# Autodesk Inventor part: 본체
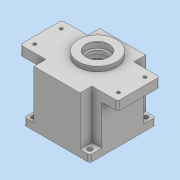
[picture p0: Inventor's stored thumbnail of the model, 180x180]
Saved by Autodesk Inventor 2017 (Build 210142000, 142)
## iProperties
Part Number: 본체
Material: 일반
Document SubType Name: Modeling
Designer: user
Density: 1 g/cm^3
Appearance: 기본값
Mass: 324.576 g
Surface Area: 793.925 cm^2
Volume: 324.576 cm^3
Author: user
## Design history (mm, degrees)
sketch "스케치1"
  geometry: L1 (-70, -30)-(70, -30); L2 (70, -30)-(70, 30); L3 (70, 30)-(-70, 30); L4 (-70, 30)-(-70, -30); L5 (-70, -30)-(70, 30); L6 (70, -30)-(-70, 30); L7 (-33, -47)-(33, -47); L8 (33, -47)-(33, 47); L9 (33, 47)-(-33, 47); L10 (-33, 47)-(-33, -47); L11 (-33, -47)-(33, 47); L12 (33, -47)-(-33, 47); 1 further point
  constraints: 24 end point, 4 midpoint, 4 parallel, 2 horizontal, 2 perpendicular
  dimensions: "d0" = 140 distance of L3.end L2.end; "d1" = 60 distance of L2.end L1.end; "d2" = 66 distance of L9.end L8.end; "d3" = 94 distance of L8.end L7.end
extrude "돌출1" new body sketch "스케치1" distance "d4" = 13; taper "d5" = 0 deg
sketch "스케치2"
  geometry: L1 (33, 47)-(-33, 47); L2 (-33, 47)-(-33, -47); L3 (-33, -47)-(33, -47); L4 (33, -47)-(33, 47); L5 (33, 47)-(-33, -47); L6 (-33, 47)-(33, -47); L7 (47, 30)-(-47, 30); L8 (-47, 30)-(-47, -30); L9 (-47, -30)-(47, -30); L10 (47, -30)-(47, 30); L11 (47, 30)-(-47, -30); L12 (-47, 30)-(47, -30); 1 further point
  constraints: 24 end point, 4 midpoint, 4 parallel, 2 horizontal, 2 perpendicular
  dimensions: "d6" = 66 distance of L3.end L2.end; "d7" = 94 distance of L2.end L1.end; "d8" = 94 distance of L9.end L8.end; "d9" = 60 distance of L8.end L7.end
extrude "돌출2" join sketch "스케치2" distance "d10" = 57; taper "d11" = 0 deg
sketch "스케치3"
  geometry: L1 (47, 47)-(-47, 47); L2 (-47, 47)-(-47, -47); L3 (-47, -47)-(47, -47); L4 (47, -47)-(47, 47); L5 (47, 47)-(-47, -47); L6 (-47, 47)-(47, -47); 1 further point
  constraints: 12 end point, 2 midpoint, 2 parallel, 1 horizontal, 1 perpendicular
  dimensions: "d12" = 94 distance of L3.end L2.end; "d13" = 94 distance of L2.end L1.end
extrude "돌출3" join sketch "스케치3" distance "d14" = 10; taper "d15" = 0 deg
sketch "스케치4"
  geometry: C1 r 27.5 at (0, 11); 1 further point
  constraints: 1 centre point, 1 vertical alignment
  dimensions: "d16" = 55 diameter of C1; "d17" = 11 distance of point (0, 0) C1.centre
extrude "돌출4" join sketch "스케치4" distance "d18" = 7; taper "d19" = 0 deg
sketch "스케치5"
  geometry: C1 r 16 at (0, 0); 1 further point
  constraints: 1 centre point
  dimensions: "d20" = 32 diameter of C1
extrude "돌출5" cut sketch "스케치5" distance "d21" = 8.3; taper "d22" = 0 deg
sketch "스케치6"
  geometry: C1 r 16 at (0, 0) reference; C2 r 12.5 at (0, 0); 1 further point
  constraints: 1 centre point, 1 coincident
  dimensions: "d23" = 25 diameter of C2
extrude "돌출6" cut sketch "스케치6" distance "d24" = 4.7; taper "d25" = 0 deg
sketch "스케치7"
  geometry: C1 r 43 at (0, 0); 1 further point
  constraints: 1 centre point, 1 coincident
  dimensions: "d26" = 86 diameter of C1
extrude "돌출7" cut sketch "스케치7" distance "d27" = 9; taper "d28" = 0 deg
sketch "스케치8"
  geometry: L1 (35.778, 3.994)-(39.8, 3.994); L2 (35.778, -3.994)-(39.8, -3.994); L3 (-35.778, 3.994)-(-39.8, 3.994); L4 (-35.778, -3.994)-(-39.8, -3.994); A1 r 40 centre (0, 0) between (39.8, 3.994) and (39.8, -3.994); A2 r 36 centre (0, 0) between (36, 0) and (-36, 0); A3 r 4 centre (36, 0) between (36.222, 3.994) and (36.222, -3.994); A4 r 4 centre (-36, 0) between (-36.222, -3.994) and (-36.222, 3.994); 1 further point
  constraints: 18 point on circle, 8 end point, 4 centre point, 4 point on line, 3 horizontal, 2 coincident, 2 horizontal alignment, 1 parallel
  dimensions: "d29" = 80 diameter of A1; "d30" = 72 diameter of A2; "d31" = 8 diameter of A3; "d32" = 8 diameter of A4
extrude "돌출8" cut sketch "스케치8" distance "d33" = 62; taper "d34" = 0 deg
sketch "스케치9"
  geometry: C1 r 21 at (0, 11); C2 r 15 at (0, -20); 1 further point
  constraints: 2 centre point, 2 vertical alignment
  dimensions: "d35" = 42 diameter of C1; "d36" = 30 diameter of C2; "d37" = 11 distance of point (0, 0) C1.centre; "d38" = 20 distance of C2.centre point (0, 0)
extrude "돌출9" join sketch "스케치9" distance "d39" = 7; taper "d40" = 0 deg
sketch "스케치10"
  geometry: C1 r 17.5 at (0, 11); A1 r 21 centre (0, 11) between (8.978, -7.984) and (-8.978, -7.984) reference; A2 r 15 centre (0, -20) between (-8.978, -7.984) and (8.978, -7.984) reference; 1 further point
  constraints: 1 centre point, 1 coincident
  dimensions: "d41" = 35 diameter of C1
extrude "돌출10" cut sketch "스케치10" distance "d43" = 10; taper "d44" = 0 deg
sketch "스케치11"
  geometry: C1 r 11 at (0, -20); A1 r 15 centre (0, -20) between (-8.978, -7.984) and (8.978, -7.984) reference; 1 further point
  constraints: 1 centre point, 1 coincident
  dimensions: "d45" = 22 diameter of C1
extrude "돌출11" cut sketch "스케치11" distance "d46" = 7; taper "d47" = 0 deg
sketch "스케치12"
  geometry: C1 r 9.5 at (0, 0); 1 further point
  constraints: 1 centre point
  dimensions: "d48" = 19 diameter of C1
extrude "돌출12" cut sketch "스케치12" distance "d49" = 3; taper "d50" = 0 deg
sketch "스케치13"
  geometry: 2 further points
  dimensions: "d51" = 60 horizontal distance of point (0, 0) point (60, -19); "d52" = 19 vertical distance of point (0, 0) point (60, -19)
hole "구멍1" sketch "스케치13" at (60, -19) diameter "d53" = 4.5; stored, may be unused: countersink angle "d57" = 90 deg, drill point angle "d59" = 118 deg; dims "d54" = 6, "d55" = 10, "d56" = 5, "d58" = 8
sketch "스케치14"
  geometry: 2 further points
  dimensions: "d66" = 40 horizontal distance of point (0, 0) point (40, -40); "d67" = 40 horizontal distance of point (0, 0) point (40, -40)
hole "구멍2" sketch "스케치14" at (40, -40) diameter "d68" = 7; stored, may be unused: countersink angle "d72" = 90 deg, drill point angle "d74" = 118 deg; dims "d69" = 6, "d70" = 10, "d71" = 5, "d73" = 8
sketch "스케치15"
  geometry: A1 r 4 centre (36, 0) between (36.222, 3.994) and (36.222, -3.994) reference; A2 r 4 centre (-36, 0) between (-36.222, -3.994) and (-36.222, 3.994) reference; 3 further points
  constraints: 2 coincident
hole "구멍3" sketch "스케치15" at (36, 0), (-36, 0) diameter "d81" = 3.242; stored, may be unused: countersink angle "d85" = 90 deg, drill point angle "d87" = 118 deg; dims "d82" = 7, "d83" = 10, "d84" = 5, "d86" = 9
chamfer "모따기1" distance "d88" = 0.8; stored, may be unused: second distance "d89" = 2, angle "d90" = 30 deg
fillet "모깎기1" dims "d91" = 3
fillet "모깎기2" dims "d92" = 3
fillet "모깎기3" dims "d93" = 3
chamfer "모따기2" distance "d94" = 1; stored, may be unused: second distance "d95" = 2, angle "d96" = 45 deg
chamfer "모따기3" distance "d97" = 1; stored, may be unused: second distance "d98" = 2, angle "d99" = 45 deg
chamfer "모따기4" distance "d100" = 1; stored, may be unused: second distance "d101" = 2, angle "d102" = 45 deg
sketch "스케치16"
  geometry: L1 (-11, 80)-(77, 80) reference; L2 (0, 70)-(0, 0) reference; 2 further points
  constraints: 1 other
  dimensions: "d103" = 40 distance from line of L1 point (33, 40); "d104" = 33 distance from line of point (33, 40) L2
feature "엠보싱1" sketch "스케치16" dims "d0" = 140, "d1" = 60, "d8" = 94, "d9" = 60, "d105" = 0.5, "d106" = 0
node "솔리드1"
pattern_linear "직사각형 패턴1" dims "d62" = 38, "d65" = 120
pattern_linear "직사각형 패턴2" dims "d77" = 80, "d80" = 80
